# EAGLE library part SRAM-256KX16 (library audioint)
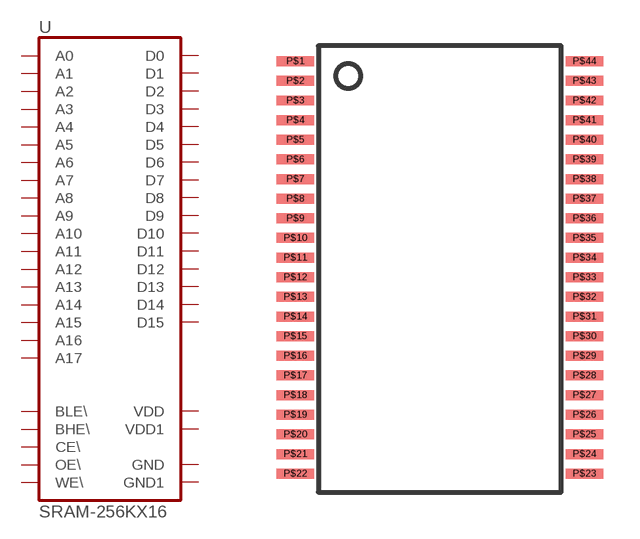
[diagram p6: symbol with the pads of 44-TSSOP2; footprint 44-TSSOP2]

Designator prefix -

## SRAM-256KX1644-TSSOP2  [44-TSSOP2]
P$1  A0  in
P$2  A1  in
P$3  A2  in
P$4  A3  in
P$5  A4  in
P$6  CE\  in
P$7  D0  hiz
P$8  D1  hiz
P$9  D2  hiz
P$10  D3  hiz
P$11  VDD  pwr
P$12  GND  pwr
P$13  D4  hiz
P$14  D5  hiz
P$15  D6  hiz
P$16  D7  hiz
P$17  WE\  in
P$18  A5  in
P$19  A6  in
P$20  A7  in
P$21  A8  in
P$22  A9  in
P$23  A10  in
P$24  A11  in
P$25  A12  in
P$26  A13  in
P$27  A14  in
P$29  D8  hiz
P$30  D9  hiz
P$31  D10  hiz
P$32  D11  hiz
P$33  VDD1  pwr
P$34  GND1  pwr
P$35  D12  hiz
P$36  D13  hiz
P$37  D14  hiz
P$38  D15  hiz
P$39  BLE\  in
P$40  BHE\  in
P$41  OE\  in
P$42  A15  in
P$43  A16  in
P$44  A17  in

## Footprint 44-TSSOP2 (pad centres in mm)
smd 1.524 x 0.406: P$1 -5.892,8.8; P$2 -5.892,8; P$3 -5.892,7.2; P$4 -5.892,6.4; P$5 -5.892,5.6; P$6 -5.892,4.8; P$7 -5.892,4; P$8 -5.892,3.2; P$9 -5.892,2.4; P$10 -5.892,1.6; P$11 -5.892,0.8; P$12 -5.892,0; P$13 -5.892,-0.8; P$14 -5.892,-1.6; P$15 -5.892,-2.4; P$16 -5.892,-3.2; P$17 -5.892,-4; P$18 -5.892,-4.8; P$19 -5.892,-5.6; P$20 -5.892,-6.4; P$21 -5.892,-7.2; P$22 -5.892,-8; P$23 5.892,-8; P$24 5.892,-7.2; P$25 5.892,-6.4; P$26 5.892,-5.6; P$27 5.892,-4.8; P$28 5.892,-4; P$29 5.892,-3.2; P$30 5.892,-2.4; P$31 5.892,-1.6; P$32 5.892,-0.8; P$33 5.892,0; P$34 5.892,0.8; P$35 5.892,1.6; P$36 5.892,2.4; P$37 5.892,3.2; P$38 5.892,4; P$39 5.892,4.8; P$40 5.892,5.6; P$41 5.892,6.4; P$42 5.892,7.2; P$43 5.892,8; P$44 5.892,8.8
